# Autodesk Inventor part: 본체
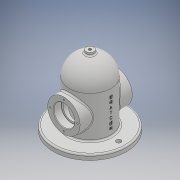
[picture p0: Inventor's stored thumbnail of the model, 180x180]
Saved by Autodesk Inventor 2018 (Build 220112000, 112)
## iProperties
Created: 2019-11
Part Number: 본체
Material: 일반
Document SubType Name: Modeling
Designer: USER
Density: 1 g/cm^3
Appearance: 기본값
Mass: 409.676 g
Surface Area: 883.272 cm^2
Volume: 409.676 cm^3
Author: USER
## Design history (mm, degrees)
sketch "스케치3"
  geometry: C1 r 31 at (0, 0); 1 further point
  constraints: 1 centre point, 1 coincident
  dimensions: "d3" = 62 diameter of C1
extrude "돌출2" new body sketch "스케치3" stored distance "d4" = 100; taper "d5" = 0 deg
node "작업 평면1"
sketch "스케치5"
  geometry: C1 r 70 at (0, 0); 1 further point
  constraints: 1 centre point, 1 coincident
  dimensions: "d7" = 140 diameter of C1
extrude "돌출3" join sketch "스케치5" distance "d8" = 10; taper "d9" = 0 deg
sketch "스케치6"
  geometry: L1 (70, -40)-(-70, -40) reference; L2 (0, -40)-(-40, -40); L3 (-40, -40)-(-40, 40); L4 (-40, 40)-(0, 40); L5 (0, 40)-(0, -40); L6 (0, 40)-(0, 80); L7 (0, 40)-(-40, 40); L8 (0, 67.168)-(0, -67.168); 2 further points
  constraints: 14 end point, 3 midpoint, 2 horizontal, 2 parallel, 2 vertical, 1 perpendicular
  dimensions: "d10" = 80 distance of L2.end L3.end; "d11" = 40 distance of L3.end L4.end
revolve "회전1" sketch "스케치6" stored, may be unused: angle "d15" = 90 deg
sketch "스케치7"
  geometry: L1 (40, 40)-(-40, 40) reference; L2 (0, 82.045)-(0, -82.045); L3 (0, 40)-(-40, 40); L4 (0, 40)-(0, 80); A1 r 40 centre (0, 40) between (0, 80) and (-40, 40); 2 further points
  constraints: 6 end point, 2 midpoint, 2 point on circle, 2 point on line, 2 vertical, 1 centre point, 1 coincident, 1 horizontal
revolve "회전2" sketch "스케치7" stored, may be unused: angle "d16" = 90 deg
node "작업 평면2"
sketch "스케치8"
  geometry: C1 r 40 at (0, 0) reference; C2 r 7.5 at (0, 0); 1 further point
  constraints: 1 centre point, 1 coincident
  dimensions: "d18" = 15 diameter of C2
extrude "돌출4" join sketch "스케치8" stored distance "d19" = 10; taper "d20" = 0 deg
sketch "스케치9"
  geometry: C1 r 16.5 at (0, 0); 1 further point
  constraints: 1 centre point, 1 coincident
  dimensions: "d21" = 33 diameter of C1
extrude "돌출5" cut sketch "스케치9" extent not by distance; stored distance "d22" = 10; taper "d23" = 0 deg
sketch "스케치10"
  geometry: C1 r 20 at (0, 0); 1 further point
  constraints: 1 centre point, 1 coincident
  dimensions: "d24" = 40 diameter of C1
extrude "돌출6" cut sketch "스케치10" distance "d25" = 15; taper "d26" = 0 deg
sketch "스케치12"
  geometry: L1 (0, 40)-(-30, 40); L2 (-30, 40)-(-30, -50); L3 (-30, -50)-(0, -50); L4 (0, -50)-(0, 40); L5 (0, 126.817)-(0, -126.817); L6 (-70, -50)-(70, -50) reference; 2 further points
  constraints: 10 end point, 2 midpoint, 2 parallel, 1 coincident, 1 horizontal, 1 perpendicular, 1 vertical
  dimensions: "d37" = 30 distance of L1.start L1.end; "d38" = 90 distance of L1.end L2.end
revolve "회전3" sketch "스케치12" stored, may be unused: angle "d39" = 90 deg
sketch "스케치13"
  geometry: L1 (30, 40)-(-30, 40) reference; L2 (0, 40)-(0, 70); L3 (0, 40)-(-30, 40); L4 (0, 70)-(0, 40); L5 (0, 40)-(-30, 40); L6 (0, 99.673)-(0, -99.673); A1 r 30 centre (0, 40) between (0, 70) and (-30, 40); 2 further points
  constraints: 10 end point, 2 midpoint, 2 point on circle, 1 centre point, 1 coincident, 1 vertical
  dimensions: "d40" = 90 deg angle of L2 L3
revolve "회전4" sketch "스케치13" stored, may be unused: angle "d41" = 90 deg
sketch "스케치15"
  geometry: C1 r 7.5 at (0, 0) reference; C2 r 7.5 at (0, 0) reference; 2 further points
  constraints: 1 coincident
hole "구멍1" sketch "스케치15" at (0, 0) diameter "d42" = 5.188; stored, may be unused: countersink angle "d46" = 90 deg, drill point angle "d48" = 118 deg; dims "d43" = 30, "d44" = 4, "d45" = 2, "d47" = 30
sketch "스케치16"
  geometry: 2 further points
  constraints: 1 vertical alignment
  dimensions: "d49" = 26 distance of point (0, 0) point (0, 26)
hole "구멍2" sketch "스케치16" at (0, 26) diameter "d50" = 3.242; stored, may be unused: countersink angle "d54" = 90 deg, drill point angle "d56" = 118 deg; dims "d51" = 8, "d52" = 4, "d53" = 2, "d55" = 10
sketch "스케치17"
  geometry: C1 r 55 at (0, 0); C2 r 4.5 at (-55, 0); C3 r 4.5 at (55, 0); 1 further point
  constraints: 3 centre point, 2 horizontal alignment, 1 coincident
  dimensions: "d60" = 110 diameter of C1; "d61" = 9 diameter of C2; "d62" = 9 diameter of C3; "d63" = 55 distance of point (0, 0) C2.centre; "d64" = 55 distance of point (0, 0) C3.centre
extrude "돌출7" cut sketch "스케치17" distance "d65" = 15; taper "d66" = 0 deg
fillet "모깎기1" dims "d67" = 0.3
chamfer "모따기1" distance "d68" = 1; stored, may be unused: second distance "d69" = 2, angle "d70" = 45 deg
fillet "모깎기2" dims "d71" = 3
fillet "모깎기3" dims "d72" = 3
fillet "모깎기4" dims "d73" = 3
fillet "모깎기5" dims "d74" = 3
node "작업 평면3"
sketch "스케치19"
  geometry: L1 (-70, -50)-(70, -50) reference; 2 further points
  constraints: 1 coincident, 1 other
  dimensions: "d75" = 50 distance from line of L1 point (0, 0)
feature "엠보싱1" sketch "스케치19" dims "d5" = 0, "d76" = 0.5, "d77" = 0
node "솔리드2"
mirror "미러1"
pattern_circular "원형 패턴1" dims angle "d58" = 360 deg
mirror "미러2"
other parameters: "d17" = -135
